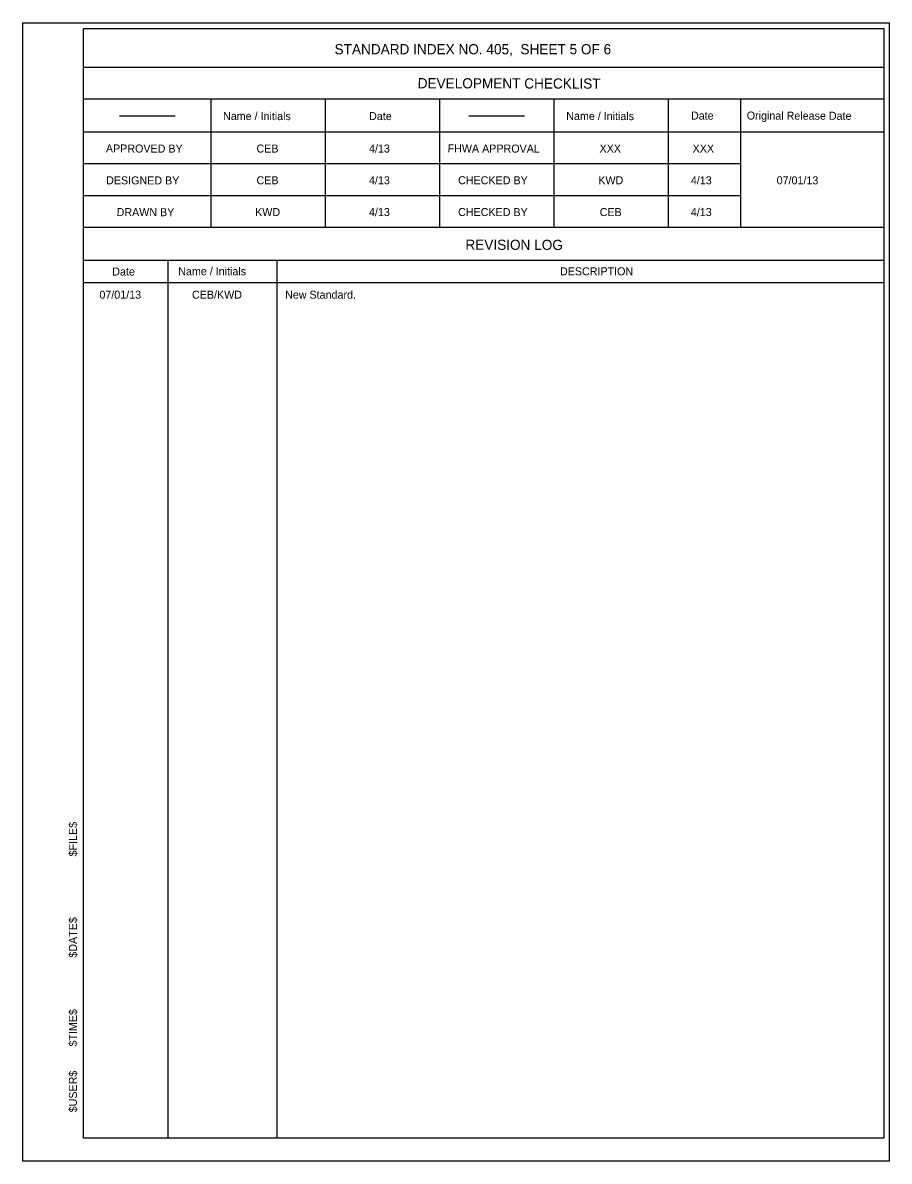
# Model space of a CAD drawing. Extents: x 1.5 to 68.7, y 0 to 31.1.
# Drawn here: x 46.92 to 68.73, y 0 to 28.67 of the extents above; entities that cross this region are included whole.
import ezdxf

# ---------------------------------------------------------------- set-up
doc = ezdxf.new("R2010")
doc.units = 0
for name, color, linetype in [('Border', 7, 'Continuous'), ('Dimension', 7, 'Continuous'), ('PlotBorder_dp', 7, 'Continuous'), ('TextStructures', 7, 'Continuous')]:
    doc.layers.add(name, color=color, linetype=linetype)

msp = doc.modelspace()

# ---------------------------------------------------------------- linework, layer by layer
at = {"layer": 'Border'}
for p, q in [((68.593, 27.54), (48.446, 27.54)), ((68.593, 26.74), (48.446, 26.74)), ((51.646, 26.74), (51.646, 23.512)), ((54.526, 26.74), (54.526, 23.512)), ((57.406, 26.74), (57.406, 23.512)), ((60.286, 26.74), (60.286, 23.512)), ((63.166, 26.74), (63.166, 23.512)), ((64.981, 26.74), (64.981, 23.512)), ((68.593, 25.912), (48.446, 25.912)), ((64.981, 25.112), (48.446, 25.112)), ((64.981, 24.312), (48.446, 24.312)), ((68.593, 23.512), (48.446, 23.512)), ((68.593, 22.684), (48.446, 22.684)), ((50.566, 22.684), (50.566, 0.578)), ((53.309, 22.684), (53.309, 0.578)), ((68.593, 22.121), (48.446, 22.121))]:
    msp.add_line(p, q, dxfattribs=at)
msp.add_lwpolyline([(48.446, 28.521), (68.593, 28.521), (68.593, 0.578), (48.446, 0.578)], close=True, dxfattribs=at)
at = {"layer": 'Dimension'}
for p, q in [((50.751, 26.312), (49.347, 26.312)), ((59.547, 26.312), (58.144, 26.312))]:
    msp.add_line(p, q, dxfattribs=at)
at = {"layer": 'PlotBorder_dp'}
msp.add_line((46.915, 0), (46.915, 0), dxfattribs=at)
msp.add_lwpolyline([(46.915, 28.667), (68.729, 28.667), (68.729, 0), (46.915, 0)], close=True, dxfattribs=at)

# ---------------------------------------------------------------- texts
at = {"layer": 'Dimension'}
msp.add_text('New Standard.', height=0.2016, dxfattribs=at).set_placement((53.52, 21.719))
at = {"layer": 'TextStructures'}
for s, height, p in [('STANDARD INDEX NO. 405,  SHEET 5 OF 6', 0.256, (54.765, 27.873)), ('CEB', 0.2016, (52.8, 25.399)), ('4/13', 0.2016, (55.632, 25.399)), ('XXX', 0.2016, (61.436, 25.399)), ('XXX', 0.2016, (63.779, 25.399)), ('CEB', 0.2016, (52.8, 24.599)), ('4/13', 0.2016, (55.632, 24.599)), ('KWD', 0.2016, (61.405, 24.599)), ('4/13', 0.2016, (63.735, 24.599)), ('07/01/13', 0.2016, (65.895, 24.599)), ('KWD', 0.2016, (52.765, 23.799)), ('4/13', 0.2016, (55.632, 23.799)), ('CEB', 0.2016, (61.44, 23.799)), ('4/13', 0.2016, (63.735, 23.799)), ('DESCRIPTION', 0.2016, (60.44, 22.307)), ('07/01/13', 0.2016, (48.845, 21.719)), ('CEB/KWD', 0.2016, (51.176, 21.719))]:
    msp.add_text(s, height=height, dxfattribs=at).set_placement(p)
for s, height, rotation, p in [('DEVELOPMENT CHECKLIST', 0.256, 359.8756, (56.858, 27.017)), ('Name / Initials', 0.2016, 359.8756, (51.957, 26.219)), ('Date', 0.2016, 359.8756, (55.633, 26.217)), ('Name / Initials', 0.2016, 359.8756, (60.597, 26.219)), ('Date', 0.2016, 359.8756, (63.738, 26.229)), ('Original Release Date', 0.2016, 359.8756, (65.142, 26.229)), ('APPROVED BY', 0.2016, 359.8756, (49.008, 25.401)), ('FHWA APPROVAL', 0.2016, 359.8756, (57.611, 25.401)), ('DESIGNED BY', 0.2016, 359.8756, (49.014, 24.599)), ('CHECKED BY', 0.2016, 359.8756, (57.875, 24.601)), ('DRAWN BY', 0.2016, 359.8756, (49.278, 23.799)), ('CHECKED BY', 0.2016, 359.8756, (57.875, 23.801)), ('REVISION LOG', 0.256, 359.8756, (58.059, 22.951)), ('Date', 0.2016, 359.8756, (49.168, 22.302)), ('Name / Initials', 0.2016, 359.8756, (50.829, 22.311)), ('$FILE$', 0.2016, 90, (48.279, 7.675)), ('$DATE$', 0.2016, 90, (48.279, 5.126)), ('$TIME$', 0.2016, 90, (48.279, 2.888)), ('$USER$', 0.2016, 90, (48.279, 1.231))]:
    msp.add_text(s, height=height, rotation=rotation, dxfattribs=at).set_placement(p)

doc.saveas('drawing.dxf')
